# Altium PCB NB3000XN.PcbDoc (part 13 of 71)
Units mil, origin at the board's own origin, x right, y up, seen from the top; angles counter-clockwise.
Board outline 9527.56 x 6929.77 mil, 6 copper layers (Top Layer, GND+SHIELD, MidLayer1, MidLayer2, P2 - 3V3+5V0, Bottom Layer), stack 62.375 mil thick; 832 components, 1027 nets, 4655 pads, 4981 vias.
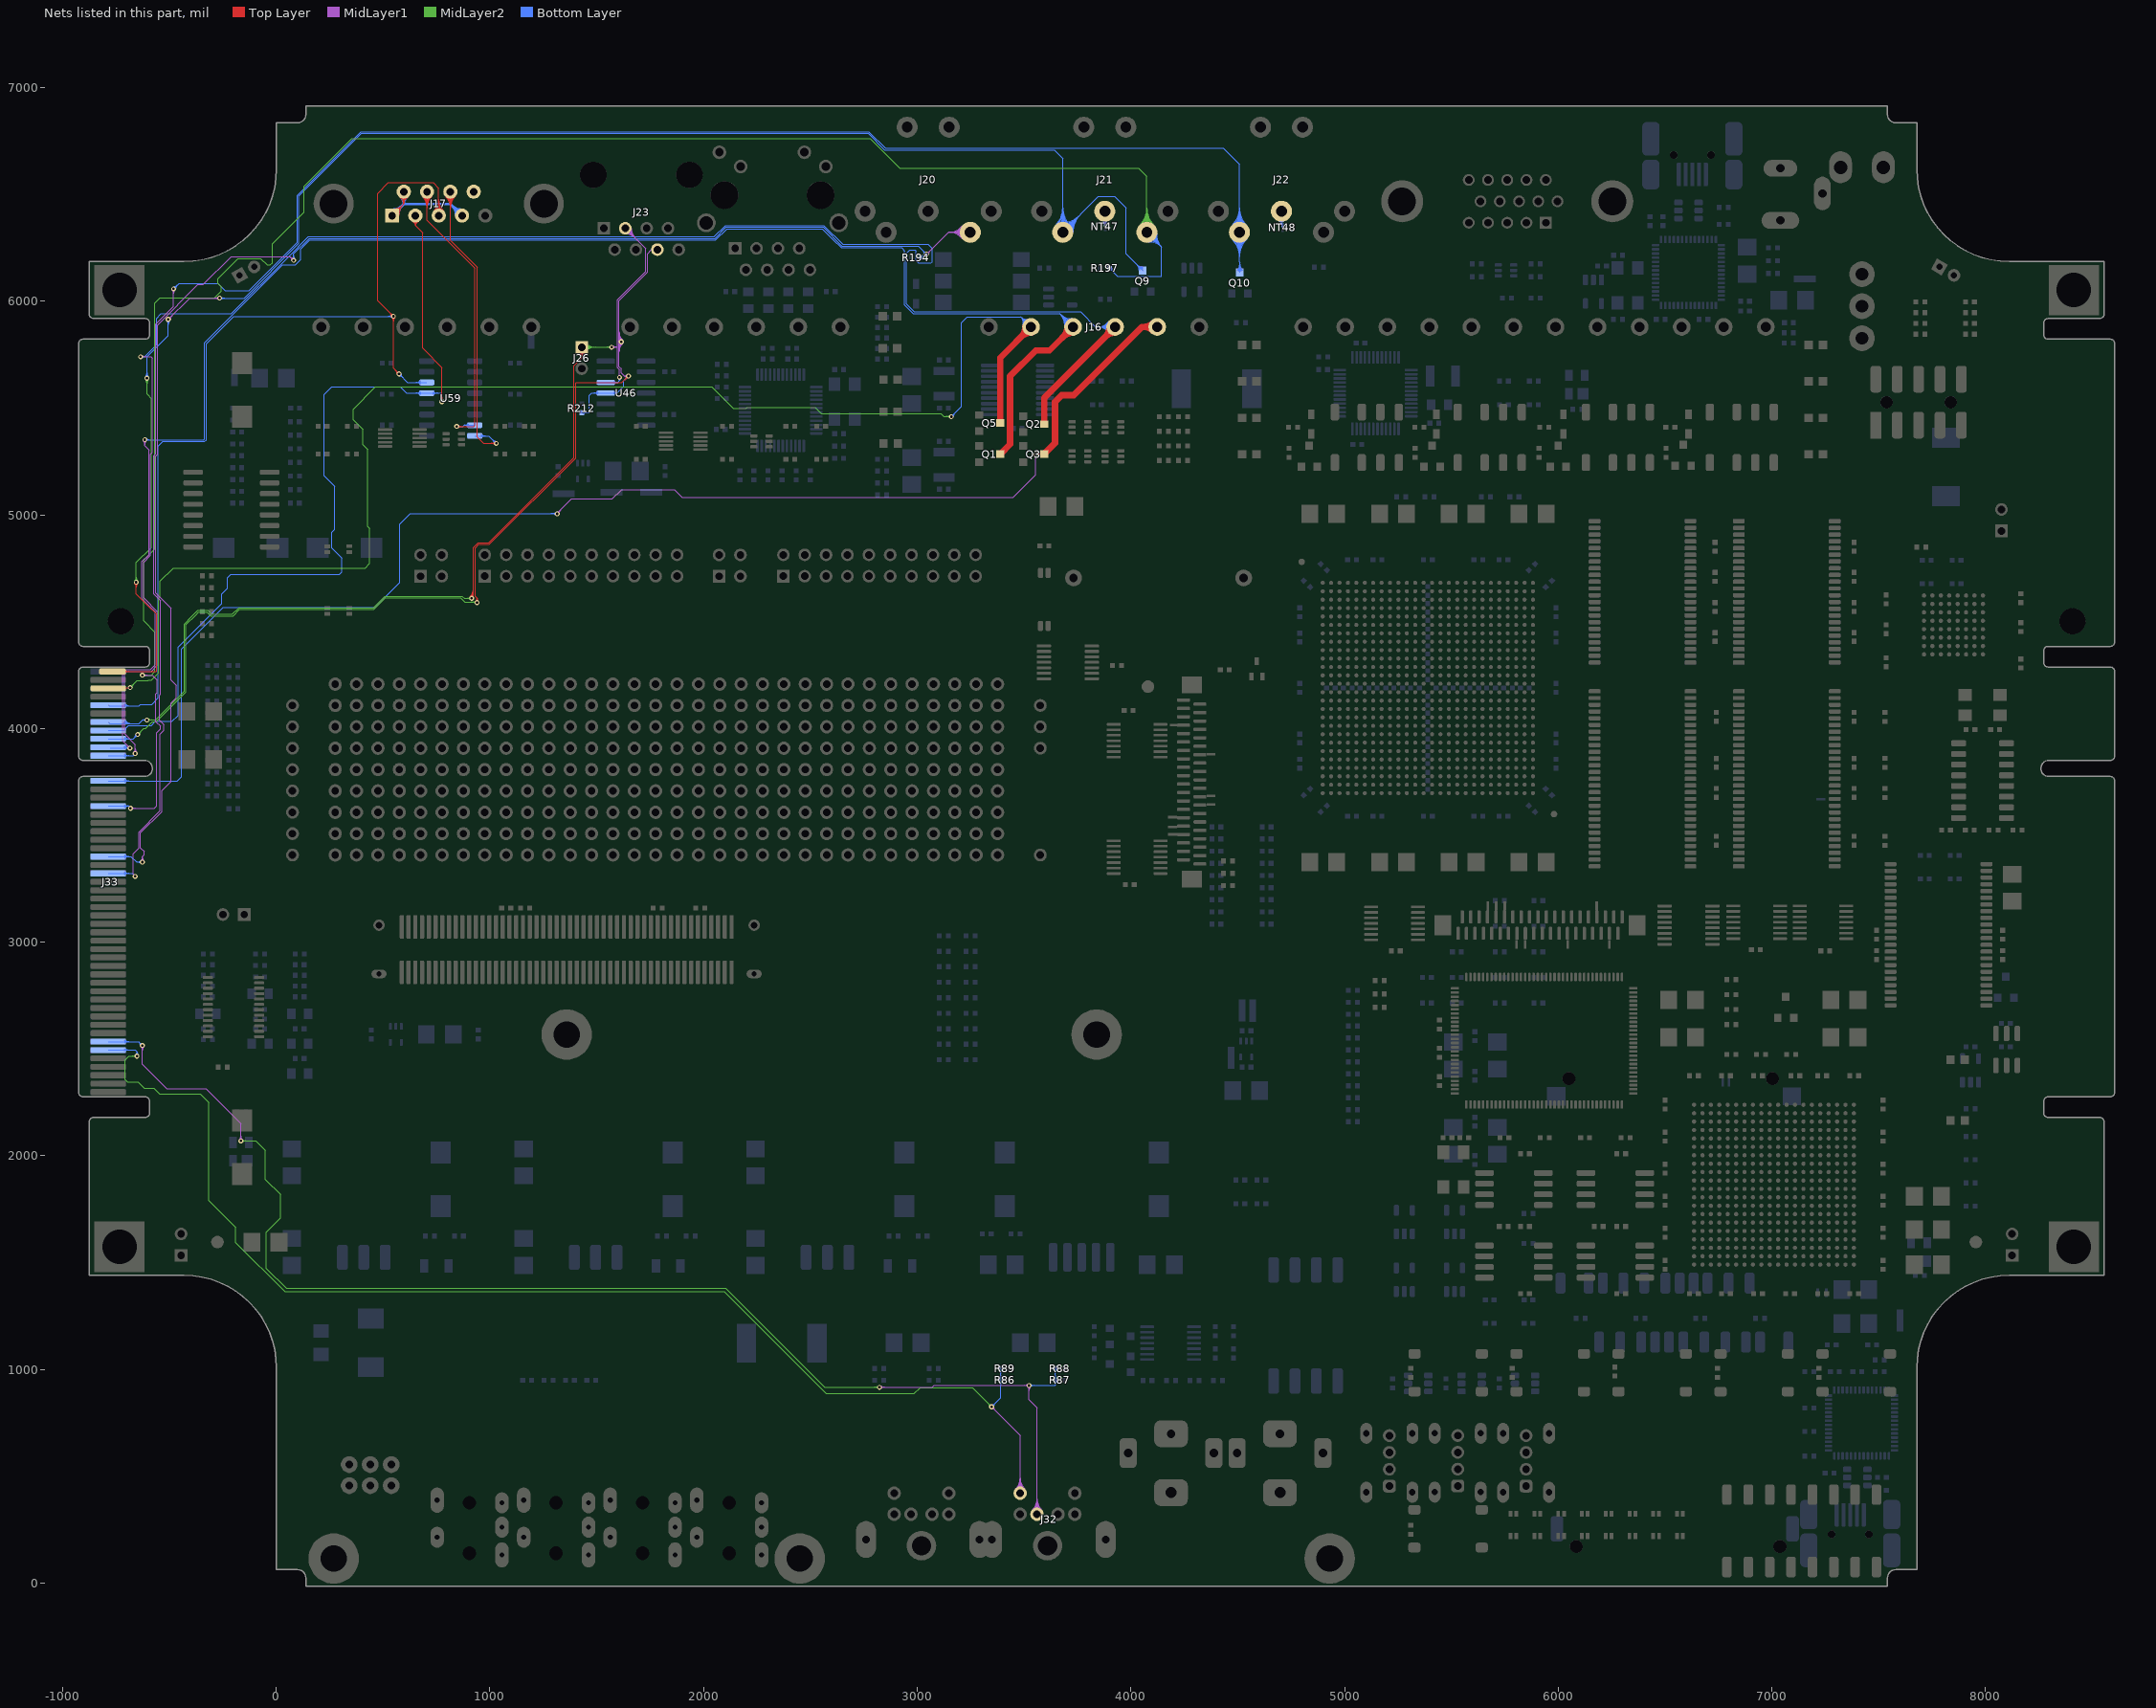
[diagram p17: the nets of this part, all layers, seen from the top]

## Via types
v1: diameter 23, hole 11.81, Top Layer to Bottom Layer, 3672 vias
v2: diameter 26, hole 11.81, Top Layer to Bottom Layer, 461 vias
v3: diameter 19, hole 11.81, Top Layer to Bottom Layer, tented both sides, 396 vias
v4: diameter 23.62, hole 11.81, Top Layer to Bottom Layer, 288 vias
v5: diameter 20, hole 11.81, Top Layer to Bottom Layer, 91 vias
v6: diameter 23, hole 11.81, Top Layer to Bottom Layer, tented both sides, 50 vias
v7: diameter 31, hole 11.81, Top Layer to Bottom Layer, 15 vias
v8: diameter 27.56, hole 11.81, Top Layer to Bottom Layer, tented both sides, 4 vias
v9: diameter 29, hole 11.81, Top Layer to Bottom Layer, 3 vias
v10: diameter 21, hole 11.81, Top Layer to Bottom Layer, 1 vias

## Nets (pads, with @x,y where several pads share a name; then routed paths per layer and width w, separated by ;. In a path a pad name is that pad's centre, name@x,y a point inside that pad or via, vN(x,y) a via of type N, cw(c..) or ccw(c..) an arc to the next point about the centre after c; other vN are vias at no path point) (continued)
ATE.MIDI#.MIDI_RX_P: J20.4 J33.B21 R194.2 | length 8244.9
  MidLayer1 w4: v1@-633.19,3381.76 ccw(c-649.41,3397.98) -626.48,3397.98 ccw(c-603.54,3397.98) v1@-619.76,3381.76 ; v1@-630.36,3378.93 ccw(c-639.75,3388.32) -626.48,3388.32 ccw(c-613.2,3388.32) v1@-622.59,3378.93 ; v1(-626.48,3375.04) -626.48,3401.67 -618.14,3410 -618.14,3425.04 -634.81,3441.71 -634.81,3511.5 -534.81,3611.5 -534.81,3710 -492.81,3752 -492.81,4119.88 -468,4144.69 -468,4203 -492.81,4227.81 -492.81,4562.43 -564.14,4633.76 -564.14,5274.8 -555.52,5283.43 -555.52,5889.67 -367.38,6077.81 -342.19,6077.81 -211.05,6208.95 64.61,6208.95 v1(81.86,6191.71) ; v1@72.36,6191.71 ccw(c49.42,6191.71) 65.64,6207.93 ccw(c81.86,6224.14) v1@81.86,6201.21 ; v1@76.36,6191.71 ccw(c63.08,6191.71) 72.47,6201.1 ccw(c81.86,6210.49) v1@81.86,6197.21 ; v1(3043.52,6220.04) 3146.42,6322.94 ; v1@3043.52,6225.54 ccw(c3043.52,6238.82) 3052.91,6229.43 ccw(c3062.3,6220.04) v1@3049.02,6220.04 ; v1@3043.52,6229.54 ccw(c3043.52,6252.48) 3059.74,6236.26 ccw(c3075.96,6220.04) v1@3053.02,6220.04 ; J20.4@3212.29,6292.42 ccw(c3146.42,6236.61) 3146.42,6322.94 ; J20.4@3212.29,6353.46 cw(c3146.42,6409.26) 3146.42,6322.94 ; J20.4@3215.34,6295 ccw(c3155.06,6243.93) 3155.06,6322.94 ccw(c3155.06,6401.95) J20.4@3215.34,6350.87 ; J20.4@3218.39,6297.59 ccw(c3163.69,6251.24) 3163.69,6322.94 ccw(c3163.69,6394.63) J20.4@3218.39,6348.29 ; J20.4@3221.44,6300.17 ccw(c3172.32,6258.55) 3172.32,6322.94 ccw(c3172.32,6387.32) J20.4@3221.44,6345.7 ; J20.4@3224.49,6302.76 ccw(c3180.95,6265.87) 3180.95,6322.94 ccw(c3180.95,6380.01) J20.4@3224.49,6343.11 ; J20.4@3227.55,6305.35 ccw(c3189.58,6273.18) 3189.58,6322.94 ccw(c3189.58,6372.69) J20.4@3227.54,6340.53 ; J20.4@3230.6,6307.93 ccw(c3198.22,6280.5) 3198.22,6322.94 ccw(c3198.21,6365.38) J20.4@3230.6,6337.94 ; J20.4@3248.31,6322.94 3146.42,6322.94
  Bottom Layer w4: J33.B21@-785.98,3400.89 -680,3400.89 -654.15,3375.04 v1(-626.48,3375.04) ; J33.B21@-711.58,3395.39 cw(c-698.3,3382.11) -698.3,3400.89 cw(c-698.3,3419.67) J33.B21@-711.58,3406.39 ; J33.B21@-708.76,3392.56 cw(c-688.65,3372.45) -688.65,3400.89 cw(c-688.65,3429.33) J33.B21@-708.76,3409.22 ; v1@-633.19,3368.32 ccw(c-649.41,3352.11) -649.41,3375.04 ccw(c-649.41,3397.98) v1@-633.19,3381.76 ; v1@-630.36,3371.15 ccw(c-639.75,3361.76) -639.75,3375.04 ccw(c-639.75,3388.32) v1@-630.36,3378.93 ; v1@75.14,6198.43 ccw(c58.92,6214.64) 81.86,6214.64 ccw(c104.79,6214.64) v1@88.57,6198.43 ; v1@77.97,6195.6 ccw(c68.58,6204.99) 81.86,6204.99 ccw(c95.14,6204.99) v1@85.75,6195.6 ; v1@82.73,6192.58 v1(81.86,6191.71) 81.86,6222.06 154.8,6295 2053.69,6295 2105.69,6347 2559.31,6347 2647.61,6258.71 3004.86,6258.71 v1(3043.52,6220.04) ; R194.2@3015.33,6202.95 ccw(c3019.84,6216.35) 3029.84,6206.35 ; R194.2@3016.18,6205 3028.48,6205 v1(3043.52,6220.04) ; R194.2@3016.6,6206.74 ccw(c3022.13,6223.18) 3034.4,6210.92 ; R194.2@3017.88,6210.53 ccw(c3024.43,6230.01) v1@3038.96,6215.48 ; R194.2@3019.15,6214.32 ccw(c3026.73,6236.83) v1(3043.52,6220.04) ; v1@3034.02,6220.04 ccw(c3011.09,6220.04) 3027.31,6236.26 ccw(c3043.52,6252.48) v1@3043.52,6229.54 ; v1@3038.02,6220.04 ccw(c3024.75,6220.04) 3034.14,6229.43 ccw(c3043.52,6238.82) v1@3043.52,6225.54
ATE.MIDI#.MIDI_THRU_GND: J21.2 NT47.2 | length 177.4
  Bottom Layer w4: J21.2@3867.43,6375.4 cw(c3864.23,6361.77) NT47.2@3878.23,6361.77 ; J21.2@3868.35,6379.29 cw(c3865.42,6366.82) 3878.23,6366.82 cw(c3891.04,6366.82) J21.2@3888.11,6379.29 ; J21.2@3869.26,6383.19 cw(c3866.6,6371.87) 3878.23,6371.87 cw(c3889.85,6371.87) J21.2@3887.2,6383.19 ; J21.2@3878.23,6378.43 ccw(c3893.93,6378.43) NT47.2@3882.83,6367.33 ; J21.2@3878.23,6421.36 NT47.2@3878.23,6361.77 ; NT47.2@3880,6360 NT47.2@3878.23,6361.77 ; J21.2@3889.02,6375.4 ccw(c3892.23,6361.77) NT47.2@3878.23,6361.77
ATE.MIDI#.MIDI_THRU_PWR: J21.4 J33.B15 R197.2 | length 10621.3
  MidLayer1 w4: v1(-682.14,3626.71) -570,3626.71 -559.81,3636.9 -559.81,3980.44 -542.5,3997.75 -542.5,4012.25 -563,4032.75 -563,4161.81 -557.19,4167.62 -557.19,4227.19 -580.04,4250.04 v1(-626.48,4250.04) ; v1@-678.25,3622.82 cw(c-668.86,3613.43) -668.86,3626.71 cw(c-668.86,3639.99) v1@-678.25,3630.6 ; v1@-675.43,3619.99 cw(c-659.21,3603.77) -659.21,3626.71 cw(c-659.21,3649.64) v1@-675.43,3633.43 ; v1@-622.59,4246.15 cw(c-613.2,4236.76) -613.2,4250.04 cw(c-613.2,4263.32) v1@-622.59,4253.93 ; v1@-619.76,4243.32 cw(c-603.54,4227.11) -603.54,4250.04 cw(c-603.54,4272.98) v1@-619.76,4256.76
  MidLayer2 w4: v1(-626.48,4250.04) -584.81,4250.04 -568.14,4266.71 -568.14,4451.06 -620.81,4503.73 -620.81,4788.31 -568.14,4840.98 -568.14,5991.86 -542.81,6017.19 -287.62,6017.19 -257.19,6047.62 -257.19,6067.38 -272.19,6082.38 -272.19,6106.5 -177.73,6200.95 -73.19,6200.95 -42.38,6170.14 -27.62,6170.14 -17.19,6180.57 -17.19,6268.87 130,6416.06 130,6537 355,6762 2780.37,6762 2918.37,6624 4036,6624 4075.08,6584.92 J21.4@4075.08,6322.94 ; v1@-622.59,4246.15 cw(c-613.2,4236.76) -613.2,4250.04 cw(c-613.2,4263.32) v1@-622.59,4253.93 ; v1@-619.76,4243.32 cw(c-603.54,4227.11) -603.54,4250.04 cw(c-603.54,4272.98) v1@-619.76,4256.76 ; J21.4@4041.69,6356.32 ccw(c3961.1,6436.92) 4075.08,6436.92 ccw(c4189.06,6436.92) J21.4@4108.46,6356.32 ; J21.4@4044.52,6353.49 ccw(c3970.75,6427.26) 4075.08,6427.26 ccw(c4179.4,6427.26) J21.4@4105.63,6353.49 ; J21.4@4047.35,6350.66 ccw(c3980.41,6417.6) 4075.08,6417.6 ccw(c4169.75,6417.6) J21.4@4102.81,6350.66 ; J21.4@4050.18,6347.84 ccw(c3990.07,6407.95) 4075.08,6407.95 ccw(c4160.09,6407.95) J21.4@4099.98,6347.84 ; J21.4@4053.01,6345.01 ccw(c3999.72,6398.29) 4075.08,6398.29 ccw(c4150.43,6398.29) J21.4@4097.15,6345.01 ; J21.4@4055.84,6342.18 ccw(c4009.38,6388.63) 4075.08,6388.63 ccw(c4140.78,6388.63) J21.4@4094.32,6342.18 ; J21.4@4058.67,6339.35 ccw(c4019.04,6378.98) 4075.08,6378.98 ccw(c4131.12,6378.98) J21.4@4091.49,6339.35
  Bottom Layer w4: J33.B15@-785.98,3637.11 -692.55,3637.11 ; J33.B15@-711.01,3632.25 cw(c-700.88,3624.13) -700.88,3637.11 cw(c-700.88,3650.1) J33.B15@-711.01,3641.98 ; J33.B15@-707.89,3629.75 cw(c-692.55,3617.45) -692.55,3637.11 ; J33.B15@-707.89,3644.48 ccw(c-692.55,3656.77) -692.55,3637.11 ; v1(-682.14,3626.71) -692.55,3637.11 ; R197.2@3901.18,6145.19 cw(c3901.18,6121.5) 3917.93,6138.25 ; R197.2@3901.18,6149.19 cw(c3901.18,6135.16) R197.2@3911.1,6145.08 ; R197.2@3901.18,6155 3938.41,6117.77 4143.77,6117.77 4143.77,6254.25 J21.4@4075.08,6322.94 ; R197.2@3906.5,6154.51 ccw(c3918.15,6154.51) R197.2@3909.91,6146.27 ; R197.2@3910.5,6154.51 ccw(c3931.81,6154.51) 3916.74,6139.44 ; J21.4@4078.32,6295.92 cw(c4083.56,6252.24) 4114.67,6283.35 cw(c4145.77,6314.45) J21.4@4102.1,6319.69 ; J21.4@4078.8,6291.95 cw(c4084.81,6241.85) 4120.49,6277.53 cw(c4156.16,6313.21) J21.4@4106.07,6319.22 ; J21.4@4079.27,6287.98 cw(c4086.06,6231.46) 4126.31,6271.71 cw(c4166.55,6311.96) J21.4@4110.04,6318.74 ; J21.4@4079.75,6284 cw(c4087.31,6221.07) 4132.13,6265.89 cw(c4176.95,6310.71) J21.4@4114.01,6318.26 ; J21.4@4080.23,6280.03 cw(c4088.55,6210.68) 4137.94,6260.07 cw(c4187.34,6309.46) J21.4@4117.98,6317.79 ; J21.4@4080.7,6276.06 cw(c4089.8,6200.29) 4143.76,6254.25 cw(c4197.73,6308.22) J21.4@4121.96,6317.31
ATE.MIDI#.MIDI_THRU_TX: J21.5 J33.A1 Q9.2 | length 10287.7
  Top Layer w4: J33.A1@-765.79,4267.54 -562.54,4267.54 -560,4270.08 -560,4535 -601.87,4576.87 ; J33.A1@-711.58,4261.53 cw(c-697.08,4247.03) -697.08,4267.54 ; J33.A1@-711.58,4272.54 ccw(c-699.53,4284.59) -699.53,4267.54 ; J33.A1@-708.76,4258.7 cw(c-687.42,4237.37) -687.42,4267.54 ; J33.A1@-708.76,4275.36 ccw(c-689.87,4294.25) -689.87,4267.54 ; v4@-661.94,4678.06 cw(c-678.69,4661.31) -655,4661.31 cw(c-631.31,4661.31) v4@-648.06,4678.06 ; v4@-659.11,4680.89 cw(c-669.03,4670.97) -655,4670.97 cw(c-640.97,4670.97) v4@-650.89,4680.89 ; v4(-655,4685) -655,4629.88 -602,4576.87 ; J21.5@3681.38,6322.94 J21.5@3681.86,6322.94
  MidLayer1 w4: v4(-505,5915) -405,6015 v1(-265,6015) ; v4@-505,5920.81 ccw(c-505,5934.84) -495.08,5924.92 ccw(c-485.16,5915) v4@-499.19,5915 ; v4@-505,5924.81 ccw(c-505,5948.5) -488.25,5931.75 ccw(c-471.5,5915) v4@-495.19,5915 ; v1@-271.72,6008.28 ccw(c-287.94,5992.06) -287.94,6015 ccw(c-287.94,6037.93) v1@-271.72,6021.72 ; v1@-268.89,6011.11 ccw(c-278.28,6001.72) -278.28,6015 ccw(c-278.28,6028.28) v1@-268.89,6018.89
  MidLayer2 w4: v4@-661.94,4691.94 ccw(c-678.69,4708.69) -655,4708.69 ccw(c-631.31,4708.69) v4@-648.06,4691.94 ; v4@-659.11,4689.11 ccw(c-669.03,4699.03) -655,4699.03 ccw(c-640.97,4699.03) v4@-650.89,4689.11 ; v4(-655,4685) -655,4776.75 -584.48,4847.28 -584.48,5544.48 -605,5565 v4(-605,5640) ; v4@-611.94,5633.06 cw(c-628.69,5616.31) -605,5616.31 cw(c-581.31,5616.31) v4@-598.06,5633.06 ; v4@-609.11,5635.89 cw(c-619.03,5625.97) -605,5625.97 cw(c-590.97,5625.97) v4@-600.89,5635.89
  Bottom Layer w4: v4@-611.94,5646.94 ccw(c-628.69,5663.69) -605,5663.69 ccw(c-581.31,5663.69) v4@-598.06,5646.94 ; v4@-609.11,5644.11 ccw(c-619.03,5654.03) -605,5654.03 ccw(c-590.97,5654.03) v4@-600.89,5644.11 ; v4(-605,5640) -605,5740 -505,5840 v4(-505,5915) ; v4@-511.94,5908.06 cw(c-528.69,5891.31) -505,5891.31 cw(c-481.31,5891.31) v4@-498.06,5908.06 ; v4@-509.11,5910.89 cw(c-519.03,5900.97) -505,5900.97 cw(c-490.97,5900.97) v4@-500.89,5910.89 ; v1(-265,6015) -150.2,6015 106.52,6271.73 106.52,6493.08 399.44,6786 2770.06,6786 2847.35,6708.71 3641.29,6708.71 3681.38,6668.62 J21.5@3681.38,6322.94 3848.44,6490 3925,6490 3977,6438 3977,6222.21 Q9.2@4055,6144.21 ; v1@-261.11,6011.11 cw(c-251.72,6001.72) -251.72,6015 cw(c-251.72,6028.28) v1@-261.11,6018.89 ; v1@-258.28,6008.28 cw(c-242.07,5992.06) -242.07,6015 cw(c-242.07,6037.93) v1@-258.28,6021.72 ; J21.5@3647.99,6356.32 ccw(c3567.4,6436.92) 3681.38,6436.92 ccw(c3795.36,6436.92) J21.5@3714.76,6356.32 ; J21.5@3650.82,6353.49 ccw(c3577.05,6427.26) 3681.38,6427.26 ccw(c3785.7,6427.26) J21.5@3711.93,6353.49 ; J21.5@3653.65,6350.66 ccw(c3586.71,6417.6) 3681.38,6417.6 ccw(c3776.05,6417.6) J21.5@3709.11,6350.66 ; J21.5@3656.48,6347.84 ccw(c3596.37,6407.95) 3681.38,6407.95 ccw(c3766.39,6407.95) J21.5@3706.28,6347.84 ; J21.5@3659.31,6345.01 ccw(c3606.02,6398.29) 3681.38,6398.29 ccw(c3756.73,6398.29) J21.5@3703.45,6345.01 ; J21.5@3662.14,6342.18 ccw(c3615.68,6388.63) 3681.38,6388.63 ccw(c3747.08,6388.63) J21.5@3700.62,6342.18 ; J21.5@3664.96,6339.35 ccw(c3625.34,6378.98) 3681.38,6378.98 ccw(c3737.42,6378.98) J21.5@3697.79,6339.35 ; J21.5@3681.38,6346.15 ccw(c3681.38,6402.19) 3721,6362.56 ccw(c3760.63,6322.94) J21.5@3704.59,6322.94 ; J21.5@3681.38,6350.15 ccw(c3681.38,6415.85) 3727.83,6369.39 ccw(c3774.29,6322.94) J21.5@3708.59,6322.94 ; J21.5@3681.38,6354.15 ccw(c3681.38,6429.5) 3734.66,6376.22 ccw(c3787.94,6322.94) J21.5@3712.59,6322.94 ; J21.5@3681.38,6358.15 ccw(c3681.38,6443.16) 3741.49,6383.05 ccw(c3801.6,6322.94) J21.5@3716.59,6322.94 ; J21.5@3681.38,6362.15 ccw(c3681.38,6456.82) 3748.32,6389.88 ccw(c3815.26,6322.94) J21.5@3720.59,6322.94 ; J21.5@3681.38,6366.15 ccw(c3681.38,6470.47) 3755.15,6396.71 ccw(c3828.92,6322.94) J21.5@3724.59,6322.94 ; J21.5@3681.38,6370.15 ccw(c3681.38,6484.13) 3761.97,6403.53 ccw(c3842.57,6322.94) J21.5@3728.59,6322.94 ; 4026.49,6172.72 ccw(c4055,6201.23) Q9.2@4055,6160.91 ; 4028.87,6170.35 cw(c4003.72,6145.2) Q9.2@4039.28,6145.2 ; 4033.32,6165.89 ccw(c4055,6187.58) Q9.2@4055,6156.91 ; 4035.69,6163.52 cw(c4017.37,6145.2) Q9.2@4043.28,6145.2 ; Q9.2@4040.15,6159.07 ccw(c4055,6173.92) Q9.2@4055,6152.91
ATE.MIDI#.MIDI_TX_GND: J22.2 NT48.2 | length 220
  Bottom Layer w4: J22.2@4692.9,6375.73 cw(c4688.73,6360) NT48.2@4705,6360 ; J22.2@4693.93,6379.59 cw(c4690.11,6365.2) 4705,6365.2 cw(c4719.89,6365.2) J22.2@4716.07,6379.59 ; J22.2@4694.95,6383.46 cw(c4691.49,6370.4) 4705,6370.4 cw(c4718.51,6370.4) J22.2@4715.05,6383.46 ; 4705,6371.57 ccw(c4722.07,6371.57) NT48.2@4710,6359.5 ; J22.2@4705,6381.23 ccw(c4731.73,6381.23) NT48.2@4712.83,6362.33 ; J22.2@4705,6421.36 NT48.2@4705,6360 ; NT48.2@4710,6355 NT48.2@4705,6360 ; J22.2@4717.1,6375.73 ccw(c4721.27,6360) NT48.2@4705,6360
ATE.MIDI#.MIDI_TX_N: J22.5 J33.B23 Q10.2 | length 11219.6
  MidLayer1 w4: v1(-659.81,3308.37) -669.14,3317.71 -669.14,3415.04 -643.14,3441.04 -643.14,3514.48 -543.14,3614.48 -543.14,3974.48 -526.5,3991.12 -526.5,4018.88 -547,4039.38 -547,4155.18 -541.19,4161 -541.19,4599.5 -572.14,4630.45 -572.14,5278.11 -563.52,5286.74 -563.52,5892.99 -480.48,5976.03 v1(-480.48,6058.37) ; v1@-487.19,6051.66 cw(c-503.41,6035.44) -480.48,6035.44 cw(c-457.54,6035.44) v1@-473.76,6051.66 ; v1@-484.36,6054.49 cw(c-493.75,6045.1) -480.48,6045.1 cw(c-467.2,6045.1) v1@-476.59,6054.49
  Bottom Layer w4: J33.B23@-785.98,3322.15 -673.59,3322.15 v1(-659.81,3308.37) ; J33.B23@-711.58,3316.65 cw(c-698.3,3303.37) -698.3,3322.15 cw(c-698.3,3340.94) J33.B23@-711.58,3327.65 ; J33.B23@-708.76,3313.82 cw(c-688.65,3293.72) -688.65,3322.15 cw(c-688.64,3350.59) J33.B23@-708.76,3330.48 ; v1(-480.48,6058.37) -455.14,6083.71 -273.52,6083.71 -239.81,6050 -126.52,6050 -118.14,6058.37 98.52,6275.04 98.52,6496.39 396.13,6794 2773.37,6794 2850.66,6716.71 4433.29,6716.71 4508.15,6641.85 J22.5@4508.15,6322.94 4508.15,6184.22 4510,6182.37 Q10.2@4510,6134.21 ; v1@-480.48,6063.87 ccw(c-480.48,6077.15) -471.09,6067.76 ccw(c-461.7,6058.37) v1@-474.98,6058.37 ; v1@-480.48,6067.87 ccw(c-480.48,6090.81) -464.26,6074.59 ccw(c-448.04,6058.37) v1@-470.98,6058.37 ; J22.5@4474.77,6289.55 cw(c4394.17,6208.95) 4508.15,6208.95 cw(c4622.13,6208.96) J22.5@4541.53,6289.55 ; J22.5@4474.77,6356.32 ccw(c4394.17,6436.92) 4508.15,6436.92 ccw(c4622.13,6436.92) J22.5@4541.53,6356.32 ; J22.5@4477.59,6292.38 cw(c4403.82,6218.61) 4508.15,6218.61 cw(c4612.47,6218.61) J22.5@4538.71,6292.38 ; J22.5@4477.59,6353.49 ccw(c4403.83,6427.26) 4508.15,6427.26 ccw(c4612.47,6427.26) J22.5@4538.71,6353.49 ; J22.5@4480.42,6295.21 cw(c4413.48,6228.27) 4508.15,6228.27 cw(c4602.82,6228.27) J22.5@4535.88,6295.21 ; J22.5@4480.42,6350.66 ccw(c4413.48,6417.6) 4508.15,6417.6 ccw(c4602.82,6417.6) J22.5@4535.88,6350.66 ; J22.5@4483.25,6298.04 cw(c4423.14,6237.92) 4508.15,6237.92 cw(c4593.16,6237.93) J22.5@4533.05,6298.04 ; J22.5@4483.25,6347.84 ccw(c4423.14,6407.95) 4508.15,6407.95 ccw(c4593.16,6407.95) J22.5@4533.05,6347.84 ; J22.5@4486.08,6300.87 cw(c4432.79,6247.58) 4508.15,6247.58 cw(c4583.5,6247.58) J22.5@4530.22,6300.87 ; J22.5@4486.08,6345.01 ccw(c4432.8,6398.29) 4508.15,6398.29 ccw(c4583.5,6398.29) J22.5@4530.22,6345.01 ; J22.5@4488.91,6303.69 cw(c4442.45,6257.24) 4508.15,6257.24 cw(c4573.85,6257.24) J22.5@4527.39,6303.69 ; J22.5@4488.91,6342.18 ccw(c4442.45,6388.63) 4508.15,6388.63 ccw(c4573.85,6388.63) J22.5@4527.39,6342.18 ; J22.5@4491.74,6306.52 cw(c4452.11,6266.9) 4508.15,6266.9 cw(c4564.19,6266.9) J22.5@4524.56,6306.52 ; J22.5@4491.74,6339.35 ccw(c4452.11,6378.98) 4508.15,6378.98 ccw(c4564.19,6378.98) J22.5@4524.56,6339.35 ; Q10.2@4498.89,6146.31 ccw(c4472.06,6173.14) 4510,6173.14 ccw(c4547.94,6173.14) Q10.2@4521.11,6146.31 ; Q10.2@4501.72,6143.48 ccw(c4481.71,6163.48) 4510,6163.48 ccw(c4538.29,6163.48) Q10.2@4518.28,6143.48 ; Q10.2@4504.54,6140.65 ccw(c4491.37,6153.83) 4510,6153.83 ccw(c4528.63,6153.83) Q10.2@4515.46,6140.65
ATE.MSE#.CLOCK: J32.5 J33.B44 R86.2 R89.2 | length 6872.3
  MidLayer1 w4: v1@3348.52,815.54 cw(c3348.52,792.61) 3364.74,808.82 cw(c3380.96,825.04) v1@3358.02,825.04 ; v1@3348.52,819.54 cw(c3348.52,806.26) 3357.91,815.65 cw(c3367.3,825.04) v1@3354.02,825.04 ; v1(3348.52,825.04) 3482.05,691.52 J32.5@3482.05,421.1 ; J32.5@3461.19,441.96 ccw(c3410.84,492.31) 3482.05,492.31 ccw(c3553.26,492.31) J32.5@3502.9,441.96 ; J32.5@3464.02,439.13 ccw(c3420.49,482.66) 3482.05,482.66 ccw(c3543.6,482.66) J32.5@3500.08,439.13 ; J32.5@3466.85,436.3 ccw(c3430.15,473) 3482.05,473 ccw(c3533.94,473) J32.5@3497.25,436.3 ; J32.5@3469.68,433.47 ccw(c3439.81,463.34) 3482.05,463.34 ccw(c3524.29,463.34) J32.5@3494.42,433.47 ; J32.5@3472.5,430.65 ccw(c3449.47,453.68) 3482.05,453.68 ccw(c3514.63,453.68) J32.5@3491.59,430.65
  MidLayer2 w4: v1@-658.19,2459.99 ccw(c-674.41,2443.77) -674.41,2466.71 ccw(c-674.41,2489.64) v1@-658.19,2473.43 ; v1@-655.36,2462.82 ccw(c-664.75,2453.43) -664.75,2466.71 ccw(c-664.75,2479.99) v1@-655.36,2470.6 ; v1(-651.48,2466.71) -689.3,2466.71 -707,2449.01 -707,2357 -695,2345 -646,2345 -618.5,2317.5 -573.25,2317.5 -545.63,2289.88 -355,2289.88 -315,2249.88 -315,1790 -190,1665 -190,1593.94 39.94,1364 2095.88,1364 2559.04,900.84 2572.88,887 2985.69,887 3013.69,915 3258.56,915 v1(3348.52,825.04) ; v1@3339.02,825.04 ccw(c3316.09,825.04) 3332.31,841.26 ccw(c3348.52,857.48) v1@3348.52,834.54 ; v1@3343.02,825.04 ccw(c3329.75,825.04) 3339.14,834.43 ccw(c3348.52,843.82) v1@3348.52,830.54
  Bottom Layer w4: J33.B44@-785.98,2495.38 -695.42,2495.37 ; J33.B44@-710.56,2491.15 cw(c-702.78,2486.11) -702.78,2495.37 cw(c-702.77,2504.64) J33.B44@-710.55,2499.61 ; J33.B44@-707.2,2488.97 cw(c-695.42,2481.33) -695.42,2495.37 ; J33.B44@-707.19,2501.78 ccw(c-695.42,2509.4) -695.42,2495.37 ; -693.14,2495.37 -695.2,2495.37 ; v1@-657.41,2474.13 ccw(c-667.29,2486.47) -651.48,2486.47 ; v1(-651.48,2466.71) -651.48,2486.48 ; v1@-645.54,2474.13 cw(c-635.66,2486.47) -651.48,2486.47 ; v1(3348.52,825.04) 3390.87,867.38 R86.2@3390.87,950 R89.2@3390.87,1005 ; v1@3348.52,830.54 ccw(c3348.52,843.82) 3357.91,834.43 ccw(c3367.3,825.04) v1@3354.02,825.04 ; v1@3348.52,834.54 ccw(c3348.52,857.48) 3364.74,841.26 ccw(c3380.96,825.04) v1@3358.02,825.04 ; R86.2@3384.28,942.92 cw(c3368.37,927.01) 3390.87,927.01 cw(c3413.36,927.01) R86.2@3397.46,942.92 ; R86.2@3384.28,957.08 ccw(c3368.37,972.99) 3390.87,972.99 ccw(c3413.36,972.99) R86.2@3397.46,957.08 ; R89.2@3384.28,997.92 cw(c3368.37,982.01) 3390.87,982.01 cw(c3413.36,982.01) R89.2@3397.46,997.92 ; R86.2@3387.11,945.75 cw(c3378.02,936.67) 3390.87,936.67 cw(c3403.71,936.67) R86.2@3394.63,945.75 ; R86.2@3387.11,954.25 ccw(c3378.02,963.33) 3390.87,963.33 ccw(c3403.71,963.33) R86.2@3394.63,954.25 ; R89.2@3387.11,1000.75 cw(c3378.02,991.67) 3390.87,991.67 cw(c3403.71,991.67) R89.2@3394.63,1000.75 ; -695.42,2495.37 -695.2,2495.37 ; -695.2,2495.37 -660.37,2495.37 -651.48,2486.48
ATE.MSE#.DATA: J32.1 J33.B43 R87.2 R88.2 | length 7440.3
  MidLayer1 w4: v1@-633.19,2509.99 cw(c-649.41,2493.77) -626.48,2493.77 cw(c-603.54,2493.77) v1@-619.76,2509.99 ; v1@-630.36,2512.82 cw(c-639.75,2503.43) -626.48,2503.43 cw(c-613.2,2503.43) v1@-622.59,2512.82 ; v1(-626.48,2516.71) -626.48,2428.27 -512.42,2314.21 -328.96,2314.21 -165.27,2150.52 v1(-165.27,2070) ; v1@-171.99,2076.72 ccw(c-188.2,2092.93) -165.27,2092.93 ccw(c-142.33,2092.93) v1@-158.55,2076.72 ; v1@-169.16,2073.89 ccw(c-178.55,2083.28) -165.27,2083.28 ccw(c-151.99,2083.28) v1@-161.38,2073.89 ; v1(2823.52,916.71) 3071.67,916.71 3080,925.04 v1(3523.52,925.04) 3523.52,858.37 3560.79,821.11 J32.1@3560.79,322.68 ; v1@2827.41,912.82 cw(c2836.8,903.43) 2836.8,916.71 cw(c2836.8,929.99) v1@2827.41,920.6 ; v1@2830.24,909.99 cw(c2846.46,893.77) 2846.46,916.71 cw(c2846.46,939.64) v1@2830.24,923.43 ; v1@3516.81,931.76 cw(c3500.59,947.98) 3500.59,925.04 cw(c3500.59,902.11) 3516.81,918.32 cw(c3500.59,902.11) 3523.52,902.11 cw(c3546.46,902.11) v1@3530.24,918.32 ; v1@3519.64,928.93 cw(c3510.25,938.32) 3510.25,925.04 cw(c3510.25,911.76) 3519.64,921.15 cw(c3510.25,911.76) 3523.52,911.76 cw(c3536.8,911.76) v1@3527.41,921.15 ; J32.1@3539.93,343.53 ccw(c3489.58,393.89) 3560.79,393.89 ccw(c3632,393.89) J32.1@3581.64,343.53 ; J32.1@3542.76,340.71 ccw(c3499.23,384.23) 3560.79,384.23 ccw(c3622.34,384.23) J32.1@3578.82,340.71 ; J32.1@3545.59,337.88 ccw(c3508.89,374.57) 3560.79,374.57 ccw(c3612.68,374.57) J32.1@3575.99,337.88 ; J32.1@3548.42,335.05 ccw(c3518.55,364.92) 3560.79,364.92 ccw(c3603.03,364.92) J32.1@3573.16,335.05 ; J32.1@3551.24,332.22 ccw(c3528.21,355.26) 3560.79,355.26 ccw(c3593.37,355.26) J32.1@3570.33,332.22
  MidLayer2 w4: v1(-165.27,2070) -95,2070 -50,2025 -50,1890 21.5,1818.5 21.5,1710.66 -47,1642.16 -47,1473.57 46.57,1380 2102.51,1380 2565.8,916.71 v1(2823.52,916.71) ; v1@-161.38,2066.11 cw(c-151.99,2056.72) -151.99,2070 cw(c-151.99,2083.28) v1@-161.38,2073.89 ; v1@-158.55,2063.28 cw(c-142.33,2047.06) -142.33,2070 cw(c-142.33,2092.93) v1@-158.55,2076.72 ; v1@2816.81,909.99 ccw(c2800.59,893.77) 2800.59,916.71 ccw(c2800.59,939.64) v1@2816.81,923.43 ; v1@2819.64,912.82 ccw(c2810.25,903.43) 2810.25,916.71 ccw(c2810.25,929.99) v1@2819.64,920.6
  Bottom Layer w4: J33.B43@-785.98,2534.75 -644.52,2534.75 v1(-626.48,2516.71) ; J33.B43@-711.58,2529.25 cw(c-698.3,2515.97) -698.3,2534.75 cw(c-698.3,2553.53) J33.B43@-711.58,2540.25 ; J33.B43@-708.76,2526.42 cw(c-688.65,2506.31) -688.65,2534.75 cw(c-688.65,2563.19) J33.B43@-708.76,2543.08 ; v1@-635.98,2516.71 ccw(c-658.91,2516.71) -642.69,2532.93 ccw(c-626.48,2549.14) v1@-626.48,2526.21 ; v1@-631.98,2516.71 ccw(c-645.25,2516.71) -635.86,2526.1 ccw(c-626.48,2535.49) v1@-626.48,2522.21 ; v1(3523.52,925.04) 3644.96,925.04 3646.77,926.85 R87.2@3646.77,950 R88.2@3646.77,1005 ; v1@3527.41,921.15 cw(c3536.8,911.76) 3536.8,925.04 cw(c3536.8,938.32) v1@3527.41,928.93 ; v1@3530.24,918.32 cw(c3546.46,902.11) 3546.46,925.04 cw(c3546.46,947.98) v1@3530.24,931.76 ; R87.2@3640.18,942.92 cw(c3624.27,927.01) 3646.77,927.01 cw(c3669.27,927.01) R87.2@3653.36,942.92 ; R87.2@3640.18,957.08 ccw(c3624.27,972.99) 3646.77,972.99 ccw(c3669.27,972.99) R87.2@3653.36,957.08 ; R88.2@3640.18,997.92 cw(c3624.27,982.01) 3646.77,982.01 cw(c3669.27,982.01) R88.2@3653.36,997.92 ; R87.2@3643.01,945.75 cw(c3633.93,936.67) 3646.77,936.67 cw(c3659.61,936.67) R87.2@3650.53,945.75 ; R87.2@3643.01,954.25 ccw(c3633.93,963.33) 3646.77,963.33 ccw(c3659.61,963.33) R87.2@3650.53,954.25 ; R88.2@3643.01,1000.75 cw(c3633.93,991.67) 3646.77,991.67 cw(c3659.61,991.67) R88.2@3650.53,1000.75
ATE.PWM.OUT0: J16.2 J33.A3 Q5.2 | length 7243.5
  Top Layer w4: J33.A3@-785.98,4188.29 -702.89,4188.29 ; J33.A3@-705.51,4186.12 cw(c-702.89,4185.63) -702.89,4188.29 ; J33.A3@-705.51,4190.46 ccw(c-702.89,4190.95) -702.89,4188.29 ; v1(-683.81,4191.71) -699.48,4191.71 -702.89,4188.29
  Top Layer w30: Q5.2@3389.21,5430 3389.21,5736.45 J16.2@3532.77,5880.01 ; J16.2@3506.43,5880.01 cw(c3442.84,5880.01) 3487.81,5835.04 cw(c3532.77,5790.08) J16.2@3532.77,5853.67
  MidLayer2 w4: v1(-683.81,4191.71) -650.98,4224.54 -600.15,4224.54 -596.87,4227.81 -584.41,4227.81 -550.98,4261.24 -550.98,4608.62 -543.14,4616.46 -543.14,4690 -481.14,4752 416.74,4752 437.5,4772.76 437.5,4935 437.5,4937.25 428,4946.75 428,5305.69 405,5328.69 405,5400 360,5445 360,5495 464,5599 2039.23,5599 2063.3,5574.94 2139.52,5498.71 2198.52,5498.71 2203.36,5503.54 2523,5503.54 2551.5,5475.04 3110,5475.04 3124.78,5460.26 3160.26,5460.26 v1(3160,5460) ; v1@-683.81,4197.21 ccw(c-683.81,4210.49) -674.42,4201.1 ccw(c-665.03,4191.71) v1@-678.31,4191.71 ; v1@-683.81,4201.21 ccw(c-683.81,4224.14) -667.59,4207.93 ccw(c-651.37,4191.71) v1@-674.31,4191.71 ; 3136.44,5460.26 cw(c3136.44,5436.44) v1@3153.28,5453.28 ; 3137.69,5460.26 ccw(c3137.69,5482.31) v1@3153.28,5466.72 ; 3146.09,5460.26 cw(c3146.09,5446.09) v1@3156.11,5456.11 ; 3147.35,5460.26 ccw(c3147.35,5472.65) v1@3156.11,5463.89
  Bottom Layer w4: v1(3160,5460) 3206.86,5506.86 3206.86,5899.2 3235,5927.34 3485.43,5927.34 ; v1@3160,5465.5 ccw(c3160,5478.78) 3169.39,5469.39 ccw(c3178.78,5460) v1@3165.5,5460 ; v1@3160,5469.5 ccw(c3160,5492.43) 3176.22,5476.22 ccw(c3192.43,5460) v1@3169.5,5460 ; J16.2@3494.93,5890.77 ccw(c3459.06,5900.97) 3485.43,5927.34 ; J16.2@3498.78,5889.68 ccw(c3466.56,5898.84) 3490.25,5922.53 ccw(c3513.93,5946.22) J16.2@3523.1,5914 ; J16.2@3502.63,5888.58 ccw(c3474.05,5896.71) 3495.06,5917.72 ccw(c3516.07,5938.72) J16.2@3524.19,5910.15 ; J16.2@3506.47,5887.49 ccw(c3481.55,5894.58) 3499.87,5912.9 ccw(c3518.2,5931.23) J16.2@3525.29,5906.3 ; J16.2@3522,5917.84 cw(c3511.8,5953.71) 3485.43,5927.34 ; J16.2@3532.77,5880.01 3485.43,5927.34
ATE.PWM.OUT1: J16.3 J33.B10 Q1.2 | length 8888
  Top Layer w30: Q1.2@3389.21,5285 3435,5330.79 3435,5650 3555,5770 3619.61,5770 J16.3@3729.62,5880.01 ; J16.3@3703.28,5880.01 cw(c3639.69,5880.01) 3684.66,5835.04 cw(c3729.62,5790.08) J16.3@3729.62,5853.67
  MidLayer1 w4: v1@-694.31,3908.37 ccw(c-717.24,3908.37) -701.03,3924.59 ccw(c-684.81,3940.81) v1@-684.81,3917.87 ; v1@-690.31,3908.37 ccw(c-703.59,3908.37) -694.2,3917.76 ccw(c-684.81,3927.15) v1@-684.81,3913.87 ; v1(-684.81,3908.37) -718.14,3941.71 -718.14,4258.37 -700.48,4276.04 -588.12,4276.04 -565.19,4298.98 -565.19,4544.75 -628.81,4608.37 -628.81,4781.63 -596.14,4814.3 -596.14,5305 -615,5323.86 v1@-615,5352.35 ; v1@-621.72,5345.78 cw(c-637.94,5329.56) -615,5329.56 cw(c-592.07,5329.56) v1@-608.28,5345.78 ; v1@-618.89,5348.61 cw(c-628.28,5339.22) -615,5339.22 cw(c-601.72,5339.22) v1@-611.11,5348.61 ; v1(-615,5352.5) v1@-615,5352.35 ; v1@-614.21,5351.56 v1@-615,5352.35
  Bottom Layer w4: J33.B10@-775.67,3908.37 v1(-684.81,3908.37) cw(c-684.81,3936.98) J33.B10@-707.67,3919.78 ; J33.B10@-714.06,3914.98 ccw(c-700.84,3924.92) -700.84,3908.37 ; J33.B10@-710.87,3917.38 ccw(c-692.83,3930.95) v1@-692.83,3908.37 ; J33.B10@-708.76,3904.37 cw(c-699.1,3894.72) -699.1,3908.37 ; v1@-691.53,3901.66 ccw(c-707.74,3885.44) -707.74,3908.37 ccw(c-707.74,3931.31) v1@-691.53,3915.09 ; v1@-688.7,3904.49 ccw(c-698.09,3895.1) -698.09,3908.37 ccw(c-698.09,3921.65) v1@-688.7,3912.26 ; v1(-615,5352.5) -615,5351.78 -614.78,5351.56 -342.16,5351.56 -339.03,5351.56 -335.52,5355.08 -335.52,5804.69 29.8,6170 90,6170 115,6195 115,6243.89 158.11,6287 2057,6287 2109,6339 2556,6339 2605,6290 2644.29,6250.71 2926.83,6250.71 2941.36,6236.19 2941.36,5983.64 2982,5943 3145.68,5943 3146.03,5943.34 3666.28,5943.34 ; v1@-611.11,5356.39 ccw(c-599.47,5368.03) -599.47,5351.56 ; v1@-608.28,5345.78 cw(c-594.32,5331.82) -594.32,5351.56 ; v1@-608.28,5359.22 ccw(c-589.81,5377.69) -589.81,5351.56 ; J16.3@3690.32,5881.67 ccw(c3608.09,5885.15) 3666.28,5943.34 ; J16.3@3694.31,5881.5 ccw(c3620.45,5884.62) 3672.72,5936.9 ccw(c3725,5989.18) J16.3@3728.13,5915.31 ; J16.3@3698.31,5881.33 ccw(c3632.8,5884.1) 3679.16,5930.46 ccw(c3725.52,5976.82) J16.3@3728.29,5911.32 ; J16.3@3702.3,5881.16 ccw(c3645.16,5883.58) 3685.6,5924.02 ccw(c3726.05,5964.46) J16.3@3728.46,5907.32 ; J16.3@3706.3,5880.99 ccw(c3657.52,5883.06) 3692.04,5917.58 ccw(c3726.57,5952.11) J16.3@3728.63,5903.32 ; J16.3@3710.3,5880.82 ccw(c3669.88,5882.53) 3698.48,5911.14 ccw(c3727.09,5939.75) J16.3@3728.8,5899.33 ; J16.3@3727.96,5919.31 cw(c3724.48,6001.54) 3666.28,5943.34 ; J16.3@3729.62,5880.01 3666.28,5943.34
ATE.PWM.OUT2: J16.4 J33.B11 Q2.2 | length 9379.8
  Top Layer w30: Q2.2@3594.21,5425 3594.21,5547.75 J16.4@3926.47,5880.01 ; J16.4@3900.13,5880.01 cw(c3836.54,5880.01) 3881.51,5835.04 cw(c3926.47,5790.08) J16.4@3926.47,5853.67
  MidLayer1 w4: v1@-666.53,3890.09 ccw(c-682.74,3906.31) -659.81,3906.31 ccw(c-636.87,3906.31) v1@-653.09,3890.09 ; v1@-663.7,3887.26 ccw(c-673.09,3896.65) -659.81,3896.65 ccw(c-646.53,3896.65) v1@-655.92,3887.26 ; v1(-659.81,3883.37) -659.81,3924.81 -710.14,3975.14 -710.14,4255.06 -697.16,4268.04 -584.81,4268.04 -557.19,4295.66 -557.19,4548.06 -620.81,4611.69 -620.81,4778.31 -588.14,4810.98 -588.14,5284.74 -579.52,5293.37 -579.52,5734.52 -585.19,5740.19 -634.81,5740.19 v1(-635,5740) ; v1@-631.11,5736.11 cw(c-621.26,5726.26) -621.26,5740.19 ; v1@-631.11,5743.89 ccw(c-622.18,5752.82) -622.18,5740.19 ; v1@-628.28,5733.28 cw(c-611.61,5716.61) -611.61,5740.19 ; v1@-628.28,5746.72 ccw(c-612.52,5762.48) -612.52,5740.19
  Bottom Layer w4: J33.B11@-785.98,3873.33 -669.85,3873.33 v1(-659.81,3883.37) ; J33.B11@-711.58,3867.83 cw(c-698.3,3854.55) -698.3,3873.33 ; J33.B11@-711.58,3878.83 ccw(c-698.3,3892.12) -698.3,3873.33 ; J33.B11@-708.76,3865 cw(c-688.65,3844.9) -688.65,3873.33 cw(c-688.64,3901.77) J33.B11@-708.76,3881.66 ; v1(-635,5740) -616.31,5740 ; v1@-627.32,5734.4 cw(c-616.31,5726.37) -616.31,5740 ; v1@-627.32,5745.6 ccw(c-616.31,5753.63) -616.31,5740 ; 55,6207.48 55.96,6207.48 ; 3061,5951 3095,5951 ; J16.4@3897.86,5853 ccw(c3835.23,5793.87) 3835.23,5880.01 ; J16.4@3897.86,5907.01 cw(c3835.23,5966.14) 3835.23,5880.01 ; J16.4@3900.77,5855.75 ccw(c3844.51,5802.63) 3844.51,5880.01 ccw(c3844.51,5957.38) J16.4@3900.77,5904.27 ; J16.4@3903.68,5858.49 ccw(c3853.78,5811.38) 3853.78,5880.01 ccw(c3853.79,5948.62) J16.4@3903.68,5901.52 ; J16.4@3906.59,5861.24 ccw(c3863.06,5820.14) 3863.06,5880.01 ccw(c3863.06,5939.87) J16.4@3906.59,5898.77 ; J16.4@3909.5,5863.98 ccw(c3872.34,5828.9) 3872.34,5880.01 ccw(c3872.34,5931.11) J16.4@3909.5,5896.03 ; J16.4@3912.41,5866.73 ccw(c3881.62,5837.66) 3881.62,5880.01 ccw(c3881.62,5922.35) J16.4@3912.41,5893.28 ; J16.4@3926.47,5880.01 3835.23,5880.01 ; -616.31,5740 -560,5796.31 -560,5920 -538.29,5941.71 -209.81,5941.71 55.96,6207.48 ; 55.96,6207.48 151.48,6303 2050.37,6303 2052.38,6305.01 2102.37,6355 2562.63,6355 2650.92,6266.71 3050,6266.71 3070,6246.71 3070,6185 3065,6180 3005,6180 2995,6190 2995,6235 2990,6240 2965,6240 2949.36,6224.36 2949.36,5986.96 2985.31,5951 3095,5951 ; 3095,5951 3095.34,5951.34 3763.89,5951.34 3835.23,5880.01
ATE.PWM.OUT3: J16.5 J33.B12 Q3.2 | length 6966
  Top Layer w4: v1(3555,5285) 3555,5287.12 3556.92,5289.04 3560.96,5289.04 v1@3565,5285 ; v1@3558.89,5281.11 cw(c3568.28,5271.72) 3568.28,5285 cw(c3568.28,5298.28) v1@3558.89,5288.89 ; v1@3561.72,5278.28 cw(c3577.93,5262.06) 3577.93,5285 cw(c3577.93,5307.93) v1@3561.72,5291.72 ; Q3.2@3579.87,5276.72 ccw(c3565,5267.51) v1@3565,5285 ; Q3.2@3579.87,5293.28 cw(c3565,5302.49) v1@3565,5285 ; Q3.2@3583.27,5278.83 ccw(c3572.19,5271.96) 3572.19,5285 ccw(c3572.19,5298.04) Q3.2@3583.27,5291.17 ; Q3.2@3594.21,5285 v1@3565,5285
  Top Layer w30: Q3.2@3594.21,5285 3645,5335.79 3645,5530 3675.94,5560.94 3732.95,5560.94 4052.02,5880.01 J16.5@4123.32,5880.01 ; J16.5@4104.7,5861.38 ccw(c4059.73,5816.42) 4059.73,5880.01 ccw(c4059.73,5943.59) J16.5@4104.7,5898.63
  MidLayer1 w4: v1(1315,5005) 1315,5008.18 1315.19,5008.37 1381.86,5075.04 1573.52,5075.04 1616.86,5118.37 1863.77,5118.37 1899.61,5082.54 3449.87,5082.54 3536.79,5169.46 3555,5187.67 v1(3555,5285) ; v1@1315,5014.5 ccw(c1315,5029.75) 1325.78,5018.97 ; v1@1320.5,5005 cw(c1341.47,5005) 1326.64,5019.83 ; v1@1324.5,5005 cw(c1355.12,5005) 1333.47,5026.65 ; v1@3548.28,5278.28 cw(c3532.06,5262.06) 3555,5262.06 cw(c3577.93,5262.06) v1@3561.72,5278.28 ; v1@3551.11,5281.11 cw(c3541.72,5271.72) 3555,5271.72 cw(c3568.28,5271.72) v1@3558.89,5281.11
  Bottom Layer w4: J33.B12@-785.98,3755.22 -462.4,3755.22 -443,3774.63 -443,4372.2 -247.16,4568.04 306.7,4568.04 ; J33.B12@-711.58,3749.72 cw(c-698.3,3736.44) -698.3,3755.22 cw(c-698.3,3774.01) J33.B12@-711.58,3760.72 ; J33.B12@-708.76,3746.89 cw(c-688.65,3726.79) -688.65,3755.22 cw(c-688.65,3783.66) J33.B12@-708.76,3763.55 ; 1286.78,5007.19 cw(c1286.78,4976.78) v1@1308.28,4998.28 ; 1296.44,5007.19 cw(c1296.44,4986.44) v1@1311.11,5001.11 ; 1297.35,5007.19 ccw(c1297.35,5022.65) v1@1308.28,5011.72 ; v1(1315,5005) 1315,5008.18 1314,5007.19 627.19,5007.19 577.21,4957.21 577.21,4683.38 461.84,4568 306.75,4568 ; 306.7,4568.04 306.75,4568
ATE.RS232#.CTS: J17.8 U59.8 | length 2046.8
  Top Layer w4: J17.8@793,6490.89 cw(c739.62,6437.51) 815.11,6437.51 cw(c890.6,6437.51) J17.8@837.22,6490.89 ; J17.8@795.83,6493.72 cw(c749.28,6447.17) 815.11,6447.17 cw(c880.94,6447.17) J17.8@834.39,6493.72 ; J17.8@798.66,6496.55 cw(c758.94,6456.83) 815.11,6456.83 cw(c871.28,6456.83) J17.8@831.56,6496.55 ; J17.8@801.49,6499.38 cw(c768.59,6466.48) 815.11,6466.48 cw(c861.63,6466.48) J17.8@828.73,6499.38 ; J17.8@804.31,6502.2 cw(c778.25,6476.14) 815.11,6476.14 cw(c851.97,6476.14) J17.8@825.91,6502.2 ; J17.8@815.11,6513 815.11,6285.08 940.19,6160 940.19,5364.81 970,5335 v1(1030,5335) ; v1@1023.28,5328.28 ccw(c1007.06,5312.06) 1007.06,5335 ccw(c1007.06,5357.93) v1@1023.28,5341.72 ; v1@1026.11,5331.11 ccw(c1016.72,5321.72) 1016.72,5335 ccw(c1016.72,5348.28) v1@1026.11,5338.89
  Bottom Layer w4: U59.8@929,5370.08 994.92,5370.08 v1(1030,5335) ; U59.8@956.15,5364.58 cw(c969.43,5351.3) 969.43,5370.08 cw(c969.43,5388.86) U59.8@956.15,5375.58 ; U59.8@958.98,5361.75 cw(c979.09,5341.64) 979.09,5370.08 cw(c979.09,5398.52) U59.8@958.98,5378.41 ; v1@1020.5,5335 ccw(c997.56,5335) 1013.78,5351.22 ccw(c1030,5367.43) v1@1030,5344.5 ; v1@1024.5,5335 ccw(c1011.22,5335) 1020.61,5344.39 ccw(c1030,5353.78) v1@1030,5340.5
ATE.RS232#.DCD: J17.1 J17.4 J17.6 | length 1647.9
  Top Layer w4: J17.1@542.47,6401.19 597,6455.72 ; J17.1@542.47,6416.46 ccw(c542.47,6453.32) 568.54,6427.25 ccw(c594.6,6401.19) J17.1@557.74,6401.19 ; J17.1@542.47,6420.46 ccw(c542.47,6466.97) 575.36,6434.08 ccw(c608.26,6401.19) J17.1@561.74,6401.19 ; J17.1@542.47,6424.46 ccw(c542.47,6480.63) 582.19,6440.91 ccw(c621.91,6401.19) J17.1@565.74,6401.19 ; J17.1@542.47,6428.46 ccw(c542.47,6494.29) 589.02,6447.74 ccw(c635.57,6401.19) J17.1@569.74,6401.19 ; J17.1@542.47,6432.46 ccw(c542.47,6507.94) 595.85,6454.57 ccw(c649.23,6401.19) J17.1@573.74,6401.19 ; J17.6@580.09,6486.7 cw(c560.17,6455.72) 597,6455.72 ; J17.6@582.25,6490.06 cw(c564.88,6463.05) 597,6463.05 cw(c629.12,6463.05) J17.6@611.75,6490.06 ; J17.6@584.42,6493.43 cw(c569.59,6470.38) 597,6470.38 cw(c624.41,6470.38) J17.6@609.58,6493.43 ; J17.6@586.58,6496.79 cw(c574.3,6477.7) 597,6477.7 cw(c619.7,6477.7) J17.6@607.42,6496.79 ; J17.6@597,6513 597,6455.72 ; J17.6@613.91,6486.7 ccw(c633.83,6455.72) 597,6455.72
  Bottom Layer w12: J17.1@542.47,6401.19 596.28,6455 815.83,6455 J17.4@869.64,6401.19 ; J17.1@542.47,6416.46 ccw(c542.47,6453.32) 568.54,6427.25 ccw(c594.6,6401.19) J17.1@557.74,6401.19 ; J17.1@542.47,6428.46 ccw(c542.47,6494.29) 589.02,6447.74 ccw(c635.57,6401.19) J17.1@569.74,6401.19 ; J17.6@579.81,6491.83 cw(c550.47,6455.72) 597,6455.72 ; J17.6@597,6513 597,6455.72 ; J17.6@614.19,6491.83 ccw(c643.53,6455.72) 597,6455.72 ; J17.4@842.37,6401.19 ccw(c776.54,6401.19) 823.09,6447.74 ccw(c869.64,6494.29) J17.4@869.64,6428.46 ; J17.4@854.37,6401.19 ccw(c817.51,6401.19) 843.57,6427.25 ccw(c869.64,6453.32) J17.4@869.64,6416.46
ATE.RS232#.RI: J17.9
ATE.RS232#.RTS: J17.7 U59.7 | length 1981.6
  Top Layer w4: J17.7@683.95,6490.89 cw(c630.57,6437.51) 706.06,6437.51 cw(c781.54,6437.51) J17.7@728.17,6490.89 ; J17.7@686.78,6493.72 cw(c640.23,6447.17) 706.06,6447.17 cw(c771.89,6447.17) J17.7@725.34,6493.72 ; J17.7@689.6,6496.55 cw(c649.88,6456.83) 706.06,6456.83 cw(c762.23,6456.83) J17.7@722.51,6496.55 ; J17.7@692.43,6499.38 cw(c659.54,6466.48) 706.06,6466.48 cw(c752.57,6466.48) J17.7@719.68,6499.38 ; J17.7@695.26,6502.2 cw(c669.2,6476.14) 706.06,6476.14 cw(c742.92,6476.14) J17.7@716.85,6502.2 ; J17.7@706.06,6513 706.06,6380 930,6156.06 930,5420 924.43,5414.43 v1(845,5414.43) ; v1@848.89,5410.54 cw(c858.28,5401.15) 858.28,5414.43 cw(c858.28,5427.71) v1@848.89,5418.32 ; v1@851.72,5407.72 cw(c867.93,5391.5) 867.93,5414.43 cw(c867.93,5437.37) v1@851.72,5421.15
  Bottom Layer w4: v1(845,5414.43) 875,5414.43 880.64,5420.08 ; v1@848.89,5410.54 cw(c858.28,5401.15) 858.28,5414.43 cw(c858.28,5427.71) v1@848.89,5418.32 ; v1@851.72,5407.72 cw(c867.93,5391.5) 867.93,5414.43 cw(c867.93,5437.37) v1@851.72,5421.15 ; U59.7@898.65,5412.14 ccw(c880.65,5395.71) 880.65,5420.08 ; U59.7@898.65,5428.02 cw(c880.65,5444.45) 880.65,5420.08 ; U59.7@901.6,5414.83 ccw(c889.71,5403.98) 889.71,5420.08 ccw(c889.71,5436.17) U59.7@901.6,5425.32 ; U59.7@929,5420.08 880.64,5420.08
ATE.RS232#.RXD: J17.2 J33.B8 U59.13 | length 4453.5
  Top Layer w4: J17.2@639.05,6372.52 cw(c630.75,6353.47) 651.53,6353.47 ; J17.2@640.64,6376.19 cw(c633.41,6359.58) 651.53,6359.58 cw(c669.65,6359.58) J17.2@662.41,6376.19 ; J17.2@642.24,6379.86 cw(c636.07,6365.68) 651.53,6365.68 cw(c666.99,6365.68) J17.2@660.82,6379.86 ; J17.2@651.53,6401.19 651.53,6353.47 ; J17.2@664.01,6372.52 ccw(c672.3,6353.47) 651.53,6353.47 ; v4@768.06,5536.94 ccw(c751.31,5553.69) 775,5553.69 ccw(c798.69,5553.69) v4@781.94,5536.94 ; v4@770.89,5534.11 ccw(c760.97,5544.03) 775,5544.03 ccw(c789.03,5544.03) v4@779.11,5534.11 ; v4(775,5530) 775,5690 685,5780 685,6320 651.53,6353.47
  Bottom Layer w4: J33.B8@-785.98,3991.44 -709.81,3991.44 -705.3,3995.95 -705.3,4000.77 -691.08,4015 -583.71,4015 -565,4033.71 -487.46,4033.71 -459,4062.16 -459,4381 -255,4585 -255,4630.1 -227.31,4657.79 -227.31,4707.29 -212.56,4722.04 296.86,4722.04 306.86,4732.04 306.86,4797.04 259.52,4844.37 259.52,4919.37 273.52,4933.37 273.52,5133.37 223.52,5183.37 223.52,5563.52 260,5600 580,5600 609.92,5570.08 U59.13@704.59,5570.08 769.78,5570.08 775,5564.86 v4(775,5530) ; U59.13@674.61,5561.75 ccw(c654.5,5541.64) 654.5,5570.08 ccw(c654.5,5598.52) U59.13@674.61,5578.41 ; U59.13@677.44,5564.58 ccw(c664.16,5551.3) 664.16,5570.08 ccw(c664.16,5588.86) U59.13@677.44,5575.58 ; U59.13@731.75,5564.58 cw(c745.03,5551.3) 745.03,5570.08 cw(c745.03,5588.86) U59.13@731.75,5575.58 ; U59.13@734.57,5561.75 cw(c754.68,5541.64) 754.68,5570.08 cw(c754.68,5598.52) U59.13@734.57,5578.41 ; v4@768.06,5536.94 ccw(c751.31,5553.69) 775,5553.69 ccw(c798.69,5553.69) v4@781.94,5536.94 ; v4@770.89,5534.11 ccw(c760.97,5544.03) 775,5544.03 ccw(c789.03,5544.03) v4@779.11,5534.11
ATE.RS232#.TXD: J17.3 J33.B5 U59.14 | length 5436.2
  Top Layer w4: v4@538.71,5930 ccw(c515.03,5930) 531.78,5946.75 ccw(c548.52,5963.5) v4@548.52,5939.81 ; v4@541.59,5923.06 cw(c524.84,5906.31) 548.52,5906.31 cw(c572.21,5906.31) v4@555.46,5923.06 ; v4@542.71,5930 ccw(c528.68,5930) 538.6,5939.92 ccw(c548.52,5949.84) v4@548.52,5935.81 ; v4@544.42,5925.89 cw(c534.5,5915.97) 548.52,5915.97 cw(c562.55,5915.97) v4@552.63,5925.89 ; v4@565.19,5660 ccw(c541.5,5660) 558.25,5676.75 ccw(c575,5693.5) v4@575,5669.81 ; v4@569.19,5660 ccw(c555.16,5660) 565.08,5669.92 ccw(c575,5679.84) v4@575,5665.81 ; v4(575,5660) 548.52,5686.48 v4(548.52,5930) 475,6003.52 475,6505 525,6555 735.58,6555 760.58,6530 J17.3@760.58,6401.19 ; J17.3@738.47,6423.3 ccw(c685.1,6476.68) 760.58,6476.68 ccw(c836.07,6476.68) J17.3@782.69,6423.3 ; J17.3@741.3,6420.47 ccw(c694.75,6467.02) 760.58,6467.02 ccw(c826.41,6467.02) J17.3@779.86,6420.47 ; J17.3@744.13,6417.64 ccw(c704.41,6457.36) 760.58,6457.36 ccw(c816.76,6457.36) J17.3@777.03,6417.64 ; J17.3@746.96,6414.81 ccw(c714.07,6447.71) 760.58,6447.71 ccw(c807.1,6447.71) J17.3@774.21,6414.81 ; J17.3@749.79,6411.99 ccw(c723.72,6438.05) 760.58,6438.05 ccw(c797.44,6438.05) J17.3@771.38,6411.99
  Bottom Layer w4: J33.B5@-785.98,4109.55 -781.43,4105 -643,4105 -635,4113 -582,4113 -551.65,4143.35 -551.65,5321.91 -530,5343.56 -335.72,5343.56 -327.52,5351.76 -327.52,5685 ; J33.B5@-714.41,4112.23 ccw(c-696.97,4129.67) -696.97,4105 ; J33.B5@-711.58,4115.05 ccw(c-687.31,4139.33) -687.31,4105 ; J33.B5@-708.76,4101.22 cw(c-699.64,4092.11) -699.64,4105 ; J33.B5@-708.76,4117.88 ccw(c-677.65,4148.99) -677.65,4105 ; -327.52,5694.55 -327.52,5685 ; v4@541.59,5923.06 ccw(c524.84,5906.31) 524.84,5930 ccw(c524.84,5953.69) v4@541.59,5936.94 ; v4@544.42,5925.89 ccw(c534.5,5915.97) 534.5,5930 ccw(c534.5,5944.03) v4@544.42,5934.11 ; v4(548.52,5930) -198.89,5930 -327.52,5801.37 -327.52,5685 ; v4@575,5650.19 cw(c575,5626.5) 591.75,5643.25 cw(c608.5,5660) v4@584.81,5660 ; v4@575,5654.19 cw(c575,5640.16) 584.92,5650.08 cw(c594.84,5660) v4@580.81,5660 ; v4(575,5660) 614.92,5620.08 U59.14@704.59,5620.08 ; U59.14@674.61,5611.75 ccw(c654.5,5591.64) 654.5,5620.08 ccw(c654.5,5648.52) U59.14@674.61,5628.41 ; U59.14@677.44,5614.58 ccw(c664.16,5601.3) 664.16,5620.08 ccw(c664.16,5638.86) U59.14@677.44,5625.58
ATE.RS485#.RX_N: J23.6 J33.B9 R212.1 U46.11 | length 5669.9
  Top Layer w4: v1@933.94,4597.32 ccw(c923.3,4610.19) 940,4610.19 ; v1@936.49,4594.24 ccw(c930.33,4601.69) 940,4601.69 ccw(c949.67,4601.69) v1@943.51,4594.24 ; v1(940,4590) 940,4610.19 ; v1@946.06,4597.32 cw(c956.7,4610.19) 940,4610.19 ; v1@1639.02,5650.04 cw(c1616.09,5650.04) 1632.31,5633.82 cw(c1648.52,5617.61) v1@1648.52,5640.54 ; v1@1643.02,5650.04 cw(c1629.75,5650.04) 1639.14,5640.65 cw(c1648.52,5631.26) v1@1648.52,5644.54 ; v1(1648.52,5650.04) 1618.48,5620 1405,5620 1402.18,5617.18 1402.18,5266.05 998.13,4862 948.86,4862 931.86,4845 931.86,4618.33 940,4610.19
  MidLayer1 w4: 1605,5763.12 cw(c1662.08,5763.12) v1@1621.72,5803.48 ; 1605,5772.77 cw(c1652.42,5772.77) v1@1618.89,5806.3 ; 1605,5782.43 cw(c1642.76,5782.43) v1@1616.06,5809.13 ; 1605,5792.09 cw(c1633.11,5792.09) v1@1613.23,5811.96 ; 1605,5801.74 cw(c1623.45,5801.74) v1@1610.4,5814.79 ; 1605,5818.64 ccw(c1623.45,5818.64) v1@1610.4,5805.6 ; 1605,5828.3 ccw(c1633.11,5828.3) v1@1613.23,5808.43 ; 1605,5837.96 ccw(c1642.76,5837.96) v1@1616.06,5811.25 ; 1605,5847.61 ccw(c1652.42,5847.61) v1@1618.89,5814.08 ; 1605,5857.27 ccw(c1662.08,5857.27) v1@1621.72,5816.91 ; v1@1640.82,5644.48 ccw(c1629.96,5636.65) 1629.96,5650.04 ; v1@1640.82,5655.6 cw(c1629.96,5663.43) 1629.96,5650.04 ; v1(1648.52,5650.04) 1629.96,5650.04 ; J23.6@1784,6241.96 1756.96,6241.96 1738,6223 1738,6136.69 1605,6003.69 1605,5693.56 1614.86,5683.71 1614.86,5665.14 1629.96,5650.04
  MidLayer2 w4: v1(-648.48,3972.04) -620.17,4000.35 -610.71,4000.35 -579.06,4032 -561.28,4032 -422,4171.28 -422,4486.5 -374.19,4534.31 -363.62,4544.87 -323.41,4544.87 -306.41,4527.87 -201.62,4527.87 -171.46,4558.04 458.31,4558.04 512.08,4611.81 863.19,4611.81 882.81,4592.19 937.81,4592.19 v1(940,4590) ; v1@-648.48,3977.54 ccw(c-648.48,3990.82) -639.09,3981.43 ccw(c-629.7,3972.04) v1@-642.98,3972.04 ; v1@-648.48,3981.54 ccw(c-648.48,4004.48) -632.26,3988.26 ccw(c-616.04,3972.04) v1@-638.98,3972.04 ; 911.78,4592.19 cw(c911.78,4561.78) v1@933.28,4583.28 ; 921.44,4592.19 cw(c921.44,4571.44) v1@936.11,4586.11 ; 922.35,4592.19 ccw(c922.35,4607.65) v1@933.28,4596.72
  Bottom Layer w4: J33.B9@-785.98,3952.07 -668.44,3952.07 v1(-648.48,3972.04) ; J33.B9@-711.58,3946.57 cw(c-698.3,3933.29) -698.3,3952.07 cw(c-698.3,3970.85) J33.B9@-711.58,3957.57 ; J33.B9@-708.76,3943.74 cw(c-688.65,3923.64) -688.65,3952.07 cw(c-688.65,3980.51) J33.B9@-708.76,3960.4 ; v1@-657.98,3972.04 cw(c-680.91,3972.04) -664.69,3955.82 cw(c-648.48,3939.61) v1@-648.48,3962.54 ; v1@-653.98,3972.04 cw(c-667.25,3972.04) -657.87,3962.65 cw(c-648.48,3953.26) v1@-648.48,3966.54 ; R212.1@1430,5478.82 1463.97,5478.82 1465.19,5480.04 1465.19,5560.08 1475.19,5570.08 U46.11@1542.57,5570.08 1550,5570.08 1586.89,5570.08 1595.08,5570.08 ; R212.1@1434.25,5475.06 cw(c1443.33,5465.98) 1443.33,5478.82 cw(c1443.33,5491.66) R212.1@1434.25,5482.58 ; R212.1@1437.08,5472.23 cw(c1452.99,5456.32) 1452.99,5478.82 cw(c1452.99,5501.32) R212.1@1437.08,5485.41 ; U46.11@1504.13,5563.14 ccw(c1487.39,5546.39) 1487.39,5570.08 ccw(c1487.38,5593.76) U46.11@1504.13,5577.01 ; U46.11@1506.96,5565.97 ccw(c1497.04,5556.05) 1497.04,5570.08 ccw(c1497.04,5584.11) U46.11@1506.96,5574.19 ; U46.11@1578.52,5566.35 cw(c1586.51,5559.65) 1586.51,5570.08 cw(c1586.51,5580.5) U46.11@1578.52,5573.81 ; U46.11@1581.58,5563.78 cw(c1595.08,5552.48) 1595.08,5570.08 ; U46.11@1581.58,5576.38 ccw(c1595.08,5587.67) 1595.08,5570.08 ; v1@1639.02,5650.04 cw(c1616.09,5650.04) 1632.31,5633.82 cw(c1648.52,5617.61) v1@1648.52,5640.54 ; v1@1643.02,5650.04 cw(c1629.75,5650.04) 1639.14,5640.65 cw(c1648.52,5631.26) v1@1648.52,5644.54 ; v1(1648.52,5650.04) 1626.62,5628.13 1626.62,5601.62 1595.08,5570.08
  other v1: 1615,5810.19
ATE.RS485#.RX_P: J23.3 J26.1 J33.B7 U46.12 | length 6025.4
  Top Layer w4: v4@908.06,4616.94 ccw(c869.93,4655.07) 923.86,4655.07 ; v4@910.89,4614.11 ccw(c879.59,4645.41) 923.86,4645.41 ; v4@913.72,4611.28 ccw(c889.24,4635.76) 923.86,4635.76 ; v4(915,4610) 923.86,4618.86 923.86,4848.31 945.54,4870 994.82,4870 1394.18,5269.36 1394.18,5699.34 1429.71,5734.87 ; v4@916.55,4608.45 ccw(c898.9,4626.1) 923.86,4626.1 ; J26.1@1415.08,5761.3 cw(c1398.51,5734.87) 1429.71,5734.87 ; J26.1@1417.21,5764.69 cw(c1403.04,5742.1) 1429.71,5742.1 cw(c1456.37,5742.1) J26.1@1442.21,5764.69 ; J26.1@1419.33,5768.08 cw(c1407.58,5749.33) 1429.71,5749.33 cw(c1451.84,5749.33) J26.1@1440.08,5768.08 ; J26.1@1429.71,5784.62 1429.71,5734.87 ; J26.1@1444.33,5761.3 ccw(c1460.91,5734.87) 1429.71,5734.87
  MidLayer1 w4: v1@1570,5785 1597,5785 ; v1@1573.89,5781.3 cw(c1582.81,5772.38) 1582.81,5785 ; v1@1573.89,5789.08 ccw(c1583.75,5798.94) 1583.75,5785 ; v1@1576.72,5778.48 cw(c1592.47,5762.73) 1592.47,5785 ; v1@1576.72,5791.91 ccw(c1593.4,5808.6) 1593.4,5785 ; v1(1606.86,5644.04) 1606.86,5680.39 1597,5690.25 1597,5785 ; J23.3@1634,6314.43 cw(c1634,6247.39) 1681.41,6294.8 ; J23.3@1634,6318.43 cw(c1634,6261.05) 1674.58,6301.62 ; J23.3@1634,6322.43 cw(c1634,6274.7) 1667.75,6308.45 ; J23.3@1634,6326.43 cw(c1634,6288.36) 1660.92,6315.28 ; J23.3@1634,6341.96 1634.24,6341.96 1730,6246.2 1730,6140 1597,6007 1597,5785 ; J23.3@1649.53,6341.96 ccw(c1686.43,6341.96) 1660.33,6315.87 ; J23.3@1653.53,6341.96 ccw(c1700.08,6341.96) 1667.16,6309.04 ; J23.3@1657.53,6341.96 ccw(c1713.74,6341.96) 1673.99,6302.21 ; J23.3@1661.53,6341.96 ccw(c1727.4,6341.96) 1680.82,6295.38
  MidLayer2 w4: v4(-605,4040) -579.41,4040 -564.58,4040.01 -430,4174.59 -430,4489.81 -392.62,4527.19 -382.19,4537.62 -366.94,4552.87 -320.1,4552.87 -303.1,4535.87 -204.94,4535.87 -174.77,4566.04 455,4566.04 508.77,4619.81 869.06,4619.81 880,4608.87 913.87,4608.87 v4(915,4610) ; v4@-600.89,4035.89 cw(c-590.97,4025.97) -590.97,4040 cw(c-590.97,4054.03) v4@-600.89,4044.11 ; v4@-598.06,4033.06 cw(c-581.31,4016.31) -581.31,4040 cw(c-581.31,4063.69) v4@-598.06,4046.94 ; 888.58,4608.87 ccw(c888.58,4636.42) v4@908.06,4616.94 ; 894.04,4608.87 cw(c894.04,4589.04) v4@908.06,4603.06 ; 898.24,4608.87 ccw(c898.24,4626.76) v4@910.89,4614.11 ; J26.1@1429.71,5784.62 1495.18,5784.62 ; J26.1@1440.8,5773.76 cw(c1466.64,5748.47) 1466.64,5784.62 cw(c1466.64,5820.78) J26.1@1440.8,5795.48 ; J26.1@1443.66,5770.96 cw(c1476.15,5739.15) 1476.15,5784.62 cw(c1476.15,5830.09) J26.1@1443.66,5798.28 ; J26.1@1446.52,5768.16 cw(c1485.67,5729.84) 1485.67,5784.62 cw(c1485.67,5839.41) J26.1@1446.52,5801.08 ; J26.1@1449.38,5765.36 cw(c1495.18,5720.52) 1495.18,5784.62 ; J26.1@1449.38,5803.88 ccw(c1495.18,5848.72) 1495.18,5784.62 ; v1@1563.28,5778.48 ccw(c1547.06,5762.26) 1547.06,5785.19 ccw(c1547.06,5808.13) v1@1563.28,5791.91 ; v1@1566.11,5781.3 ccw(c1556.72,5771.92) 1556.72,5785.19 ccw(c1556.72,5798.47) v1@1566.11,5789.08 ; v1(1570,5785.19) 1495.76,5785.19 1495.18,5784.62
  Bottom Layer w4: J33.B7@-785.98,4030.81 -778.17,4023 -670,4023 -668.06,4023 -642,4023 -625,4040 ; J33.B7@-717.24,4030.66 ccw(c-698.84,4048.94) -698.84,4023 ; J33.B7@-714.4,4033.48 ccw(c-689.23,4058.49) -689.23,4023 ; J33.B7@-711.57,4036.3 ccw(c-679.61,4068.04) -679.61,4023 ; J33.B7@-708.73,4039.12 ccw(c-670,4077.58) -670,4023 ; v4@-612.76,4034 ccw(c-625,4024.52) -625,4040 ; v4@-612.76,4046 cw(c-625,4055.48) -625,4040 ; v4@-609.6,4036.44 ccw(c-616.85,4030.83) -616.85,4040 ccw(c-616.85,4049.17) v4@-609.6,4043.56 ; v4(-605,4040) -625,4040 ; U46.12@1542.57,5620.08 1598.86,5620.08 1606.86,5628.08 ; U46.12@1578.17,5615.97 cw(c1588.09,5606.05) 1588.09,5620.08 cw(c1588.09,5634.11) U46.12@1578.17,5624.19 ; U46.12@1581,5613.14 cw(c1597.75,5596.39) 1597.75,5620.08 ; U46.12@1581,5627.01 ccw(c1597.75,5643.76) 1597.75,5620.08 ; v1@1602.33,5635.69 cw(c1598.2,5628.08) 1606.86,5628.08 ; v1(1606.86,5644.04) 1606.86,5628.08 ; v1@1611.39,5635.69 ccw(c1615.52,5628.08) 1606.86,5628.08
